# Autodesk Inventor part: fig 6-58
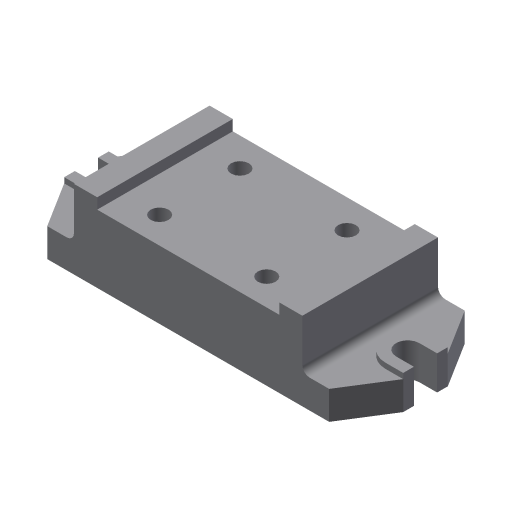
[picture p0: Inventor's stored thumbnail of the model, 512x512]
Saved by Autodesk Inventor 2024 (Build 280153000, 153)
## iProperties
Shininess: 77.0
Angle Display Precision: 2
Document Length Units: 11269
Document Angle Units: 11279
Document Time Units: 11290
Document Mass Units: 11283
Document Length Units Precision: 3
Document Angle Units Precision: 2
Created: 2001-12
Part Number: fig 6-58
Document SubType Name: Modeling
Designer: Renu Muthoo
Density: 1 g/cm^3
Material: Generic
Appearance: Default
Density: 0.0
Volumn: 0.0
Area: 0.0
PropertySet Name: Model Information
Control State: 0
Master: False
Checked Out: False
Author: Renu Muthoo
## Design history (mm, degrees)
sketch "Sketch3"
  geometry: L1 (-59.119, -24.322)-(-59.119, 19.678); L2 (-59.119, 19.678)-(-46.119, 19.678); L3 (-46.119, 19.678)-(-46.119, 13.678); L4 (-46.119, 13.678)-(55.881, 13.678); L5 (55.881, 13.678)-(55.881, 19.678); L6 (55.881, 19.678)-(68.881, 19.678); L7 (68.881, 19.678)-(68.881, -24.322); L8 (68.881, -24.322)-(-59.119, -24.322)
  constraints: 16 end point, 2 equal length
  dimensions: "d10" = 13 distance of L1.end L2.end; "d11" = 102 distance of L3.end L4.end; "d13" = 44 distance between parallel lines of L2 L8; "d14" = 6 distance of L2.end L3.end
extrude "Extrusion1" new body sketch "Sketch3" distance "d15" = 76; taper "d16" = 0 deg
sketch "Sketch4"
  geometry: L1 (0, 0)-(0, 76) reference; L2 (0, 76)-(-15, 76); L3 (-15, 76)-(-31, 50.5); L4 (-31, 50.5)-(-31, 44.5); L5 (-31, 44.5)-(-21, 44.5); L6 (-21, 31.5)-(-31, 31.5); L7 (-31, 31.5)-(-31, 25.5); L8 (-31, 25.5)-(-15, 0); L9 (-15, 0)-(0, 0); L10 (128, 76)-(0, 76) reference; L11 (0, 0)-(128, 0) reference; A1 r 6.5 centre (-21, 38) between (-21, 31.5) and (-21, 44.5)
  constraints: 16 end point, 4 equal length, 3 collinear, 3 parallel, 2 perpendicular, 2 point on circle, 2 tangent, 1 centre point
  dimensions: "d17" = 13 distance between parallel lines of L6 L5; "d18" = 25 distance of L3.end L7.end; "d19" = 10 distance of L6.start L6.end; "d20" = 15 distance of L8.end L1.start; "d21" = 16 horizontal distance of L7.end L8.end
extrude "Extrusion2" join sketch "Sketch4" distance "d22" = 16; taper "d23" = 0 deg
sketch "Sketch5"
  geometry: L1 (-159, 44.5)-(-159, 50.5) reference; L2 (-149, 44.5)-(-159, 44.5) reference; L3 (-159, 31.5)-(-149, 31.5) reference; L4 (-159, 25.5)-(-159, 31.5) reference; L5 (-159, 25.5)-(-149, 25.5); L6 (-149, 50.5)-(-159, 50.5); A1 r 6.5 centre (-149, 38) between (-149, 31.5) and (-149, 44.5) reference; A2 r 12.5 centre (-149, 38) between (-149, 25.5) and (-149, 50.5)
  constraints: 4 end point, 2 point on circle, 2 tangent, 1 centre point, 1 parallel, 1 perpendicular
extrude "Extrusion3" join sketch "Sketch5" distance "d24" = 19; taper "d25" = 0 deg
workplane "Work Plane1"
mirror "Mirror1"
fillet "Fillet1" dims "d27" = 4
sketch "Sketch6"
  geometry: L1 (0, 0)-(0, 76) reference; L2 (0, 0)-(102, 0) reference; 1 further point
  dimensions: "d28" = 20 distance from line of L1 point (20, 15); "d29" = 15 distance from line of L2 point (20, 15)
hole "Hole1" sketch "Sketch6" diameter "d30" = 10; stored, may be unused: countersink angle "d34" = 82 deg, drill point angle "d36" = 118 deg; dims "d31" = 6, "d32" = 4, "d33" = 2, "d35" = 15
sketch "Sketch7"
  geometry: C1 r 5 at (20, 15) reference; 3 further points
  constraints: 4 other
pattern_linear "Rectangular Pattern2" dims "d45" = 45, "d48" = 60
body "Solid1"
other parameters: "d26" = -64
